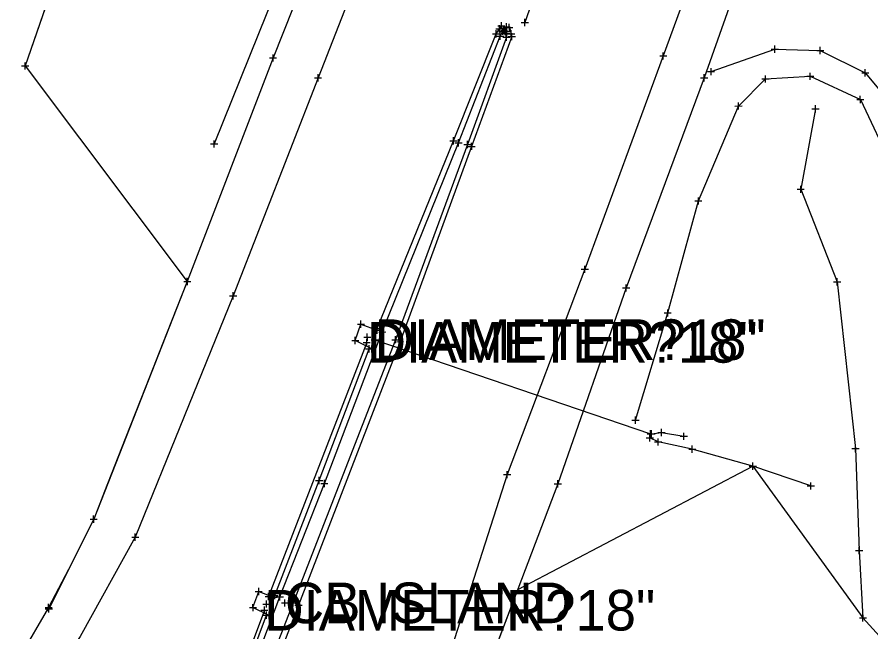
# Model space of a CAD drawing. Extents: x -1 to 1157254, y -1 to 2021979.
# Drawn here: x 1151479.8 to 1151631, y 2018989.6 to 2019098.4 of the extents above; entities that cross this region are included whole.
import ezdxf

# ---------------------------------------------------------------- set-up
doc = ezdxf.new("R2010")
doc.units = 0
for name, color, linetype in [('S_BUILDING_ANNOT', 7, 'Continuous'), ('S_CTL_TABLE', 7, 'Continuous'), ('S_DITCHLINE', 7, 'Continuous'), ('S_DRIVEWAY_ANNOT', 7, 'Continuous'), ('S_EDGE_BITUMINOUS_ANNOT', 7, 'Continuous'), ('S_EDGE_CONCRETE', 7, 'Continuous'), ('S_EDGE_CONCRETE_ANNOT', 7, 'Continuous'), ('S_EDGE_PAVEMENT', 7, 'Continuous'), ('S_ELECTRIC_UTILITIES', 7, 'Continuous'), ('S_ENV_CONSTRAINT', 7, 'Continuous'), ('S_FLAG_POLE', 7, 'Continuous'), ('S_GAS_PUMP_ISLAND_ANNOT', 7, 'Continuous'), ('S_GATE', 7, 'Continuous')]:
    doc.layers.add(name, color=color, linetype=linetype)

msp = doc.modelspace()

# ---------------------------------------------------------------- linework, layer by layer
at = {"layer": 'S_BUILDING_ANNOT'}
for p, q in [((1151565.25, 2019095.72), (1151565.24, 2019097)), ((1151565.58, 2019096.26), (1151565.58, 2019097.53)), ((1151566.5, 2019096.07), (1151566.49, 2019097.35)), ((1151567, 2019095.95), (1151566.99, 2019097.23)), ((1151569.11, 2019097.46), (1151570.38, 2019097.46)), ((1151569.75, 2019096.83), (1151569.74, 2019098.1)), ((1151569.75, 2019097.46), (1151569.75, 2019097.46)), ((1151564.01, 2019095.47), (1151565.28, 2019095.47)), ((1151564.61, 2019096.36), (1151565.88, 2019096.36)), ((1151564.65, 2019094.84), (1151564.65, 2019096.11)), ((1151564.65, 2019095.47), (1151564.65, 2019095.47)), ((1151564.94, 2019096.89), (1151566.22, 2019096.89)), ((1151565.18, 2019095.9), (1151566.45, 2019095.91)), ((1151565.25, 2019096.36), (1151565.25, 2019096.36)), ((1151565.37, 2019094.41), (1151565.36, 2019095.68)), ((1151565.42, 2019096.07), (1151566.69, 2019096.07)), ((1151565.58, 2019096.89), (1151565.58, 2019096.89)), ((1151565.64, 2019095.89), (1151566.92, 2019095.89)), ((1151565.81, 2019095.51), (1151567.09, 2019095.52)), ((1151565.82, 2019095.27), (1151565.82, 2019096.54)), ((1151565.82, 2019095.91), (1151565.82, 2019095.91)), ((1151565.86, 2019096.71), (1151567.13, 2019096.71)), ((1151565.94, 2019095.89), (1151567.21, 2019095.9)), ((1151566.06, 2019095.44), (1151566.06, 2019096.71)), ((1151566.06, 2019096.07), (1151566.06, 2019096.07)), ((1151566.28, 2019095.25), (1151566.28, 2019096.52)), ((1151566.28, 2019095.89), (1151566.28, 2019095.89)), ((1151566.36, 2019096.59), (1151567.63, 2019096.59)), ((1151566.45, 2019094.88), (1151566.45, 2019096.15)), ((1151566.45, 2019095.51), (1151566.45, 2019095.51)), ((1151566.49, 2019094.24), (1151566.49, 2019095.51)), ((1151566.5, 2019096.71), (1151566.5, 2019096.71)), ((1151566.58, 2019095.26), (1151566.57, 2019096.53)), ((1151566.57, 2019095.89), (1151566.57, 2019095.89)), ((1151566.67, 2019095.49), (1151567.94, 2019095.49)), ((1151567, 2019096.59), (1151567, 2019096.59)), ((1151567.31, 2019094.86), (1151567.31, 2019096.13)), ((1151567.31, 2019095.49), (1151567.31, 2019095.49)), ((1151567.44, 2019094.33), (1151567.44, 2019095.6)), ((1151564.73, 2019095.04), (1151566, 2019095.05)), ((1151565.36, 2019095.05), (1151565.36, 2019095.05)), ((1151565.86, 2019094.88), (1151567.13, 2019094.88)), ((1151566.49, 2019094.88), (1151566.49, 2019094.88)), ((1151566.8, 2019094.97), (1151568.08, 2019094.97)), ((1151567.44, 2019094.97), (1151567.44, 2019094.97)), ((1151613.36, 2019092.77), (1151614.64, 2019092.77)), ((1151614, 2019092.13), (1151614, 2019093.4)), ((1151614, 2019092.77), (1151614, 2019092.77)), ((1151621.42, 2019092.51), (1151622.7, 2019092.51)), ((1151622.06, 2019091.88), (1151622.06, 2019093.15)), ((1151622.06, 2019092.51), (1151622.06, 2019092.51)), ((1151524.51, 2019091.21), (1151525.78, 2019091.21)), ((1151525.15, 2019090.57), (1151525.15, 2019091.84)), ((1151525.15, 2019091.21), (1151525.15, 2019091.21)), ((1151593.63, 2019091.55), (1151594.9, 2019091.55)), ((1151594.26, 2019090.91), (1151594.26, 2019092.18)), ((1151594.26, 2019091.55), (1151594.26, 2019091.55)), ((1151602.72, 2019088.15), (1151602.71, 2019089.42)), ((1151533.12, 2019087.05), (1151533.12, 2019088.32)), ((1151601.48, 2019087.06), (1151601.48, 2019088.33)), ((1151602.08, 2019088.78), (1151603.35, 2019088.79)), ((1151602.71, 2019088.79), (1151602.71, 2019088.79)), ((1151629.4, 2019088.57), (1151630.67, 2019088.57)), ((1151630.03, 2019087.94), (1151630.03, 2019089.21)), ((1151630.03, 2019088.57), (1151630.03, 2019088.57)), ((1151532.48, 2019087.68), (1151533.75, 2019087.68)), ((1151533.12, 2019087.68), (1151533.12, 2019087.68)), ((1151600.85, 2019087.7), (1151602.12, 2019087.7)), ((1151601.48, 2019087.7), (1151601.48, 2019087.7)), ((1151620.59, 2019082.19), (1151621.86, 2019082.19)), ((1151621.23, 2019081.56), (1151621.22, 2019082.83)), ((1151621.22, 2019082.19), (1151621.22, 2019082.19)), ((1151556.46, 2019076.53), (1151557.73, 2019076.53)), ((1151557.1, 2019075.89), (1151557.09, 2019077.16)), ((1151557.09, 2019076.53), (1151557.09, 2019076.53)), ((1151557.36, 2019076.17), (1151558.64, 2019076.18)), ((1151558, 2019075.54), (1151558, 2019076.81)), ((1151558, 2019076.17), (1151558, 2019076.17)), ((1151558.94, 2019075.88), (1151560.21, 2019075.89)), ((1151559.58, 2019075.25), (1151559.58, 2019076.52)), ((1151559.58, 2019075.88), (1151559.58, 2019075.88)), ((1151560.33, 2019074.91), (1151560.32, 2019076.19)), ((1151559.69, 2019075.55), (1151560.96, 2019075.55)), ((1151560.32, 2019075.55), (1151560.32, 2019075.55)), ((1151618.59, 2019067.31), (1151618.59, 2019068.58)), ((1151617.95, 2019067.94), (1151619.23, 2019067.95)), ((1151618.59, 2019067.94), (1151618.59, 2019067.94)), ((1151579.72, 2019053.78), (1151580.99, 2019053.78)), ((1151580.36, 2019053.14), (1151580.36, 2019054.42)), ((1151580.36, 2019053.78), (1151580.36, 2019053.78)), ((1151509.34, 2019051.62), (1151510.61, 2019051.63)), ((1151509.98, 2019050.99), (1151509.97, 2019052.26)), ((1151509.97, 2019051.62), (1151509.97, 2019051.62)), ((1151625.04, 2019050.92), (1151625.04, 2019052.19)), ((1151587.05, 2019050.48), (1151588.32, 2019050.49)), ((1151587.68, 2019049.85), (1151587.68, 2019051.12)), ((1151587.68, 2019050.48), (1151587.68, 2019050.48)), ((1151624.4, 2019051.56), (1151625.67, 2019051.56)), ((1151625.04, 2019051.56), (1151625.04, 2019051.56)), ((1151517.47, 2019049.1), (1151518.74, 2019049.1)), ((1151518.11, 2019048.46), (1151518.1, 2019049.74)), ((1151518.11, 2019049.1), (1151518.11, 2019049.1)), ((1151540.08, 2019044.07), (1151541.36, 2019044.07)), ((1151540.72, 2019043.43), (1151540.72, 2019044.71)), ((1151540.72, 2019044.07), (1151540.72, 2019044.07)), ((1151542.94, 2019043.3), (1151544.21, 2019043.31)), ((1151542.97, 2019043.01), (1151544.24, 2019043.01)), ((1151543.58, 2019042.67), (1151543.58, 2019043.94)), ((1151543.58, 2019043.3), (1151543.58, 2019043.3)), ((1151543.6, 2019042.38), (1151543.6, 2019043.65)), ((1151543.6, 2019043.01), (1151543.6, 2019043.01)), ((1151543.87, 2019042.68), (1151545.14, 2019042.69)), ((1151544.51, 2019042.05), (1151544.5, 2019043.32)), ((1151544.5, 2019042.69), (1151544.5, 2019042.69)), ((1151539.08, 2019041.16), (1151540.35, 2019041.17)), ((1151539.72, 2019040.53), (1151539.71, 2019041.8)), ((1151539.71, 2019041.17), (1151539.71, 2019041.17)), ((1151541.21, 2019041.78), (1151542.48, 2019041.78)), ((1151541.21, 2019041.78), (1151542.48, 2019041.78)), ((1151541.74, 2019040.21), (1151541.74, 2019041.48)), ((1151541.74, 2019040.21), (1151541.74, 2019041.48)), ((1151541.85, 2019041.14), (1151541.84, 2019042.42)), ((1151541.85, 2019041.14), (1151541.84, 2019042.42)), ((1151541.84, 2019041.78), (1151541.84, 2019041.78)), ((1151541.84, 2019041.78), (1151541.84, 2019041.78)), ((1151542.51, 2019041.32), (1151543.78, 2019041.32)), ((1151542.51, 2019041.32), (1151543.78, 2019041.32)), ((1151543.15, 2019040.69), (1151543.15, 2019041.96)), ((1151543.15, 2019040.69), (1151543.15, 2019041.96)), ((1151543.15, 2019041.32), (1151543.15, 2019041.32)), ((1151543.15, 2019041.32), (1151543.15, 2019041.32)), ((1151546.17, 2019041.31), (1151547.45, 2019041.31)), ((1151546.81, 2019040.68), (1151546.81, 2019041.95)), ((1151546.81, 2019041.31), (1151546.81, 2019041.31)), ((1151547.64, 2019040.34), (1151547.63, 2019041.61)), ((1151541.1, 2019040.84), (1151542.38, 2019040.85)), ((1151541.1, 2019040.84), (1151542.38, 2019040.85)), ((1151541.55, 2019039.72), (1151542.83, 2019039.72)), ((1151541.74, 2019040.85), (1151541.74, 2019040.85)), ((1151541.74, 2019040.85), (1151541.74, 2019040.85)), ((1151542.02, 2019039.68), (1151543.3, 2019039.69)), ((1151542.19, 2019039.08), (1151542.19, 2019040.35)), ((1151542.19, 2019039.72), (1151542.19, 2019039.72)), ((1151542.66, 2019039.05), (1151542.66, 2019040.32)), ((1151542.66, 2019039.69), (1151542.66, 2019039.69)), ((1151547, 2019040.97), (1151548.27, 2019040.98)), ((1151547.64, 2019040.98), (1151547.64, 2019040.98)), ((1151591.38, 2019024.64), (1151592.65, 2019024.64)), ((1151591.52, 2019024.67), (1151592.8, 2019024.68)), ((1151591.89, 2019023.31), (1151591.89, 2019024.58)), ((1151592.02, 2019024), (1151592.02, 2019025.28)), ((1151592.02, 2019024.64), (1151592.02, 2019024.64)), ((1151592.16, 2019024.04), (1151592.16, 2019025.31)), ((1151592.16, 2019024.68), (1151592.16, 2019024.68)), ((1151593.32, 2019024.89), (1151594.59, 2019024.9)), ((1151593.96, 2019024.26), (1151593.96, 2019025.53)), ((1151593.96, 2019024.9), (1151593.96, 2019024.9)), ((1151597.9, 2019023.57), (1151597.89, 2019024.85)), ((1151591.25, 2019023.94), (1151592.52, 2019023.95)), ((1151591.89, 2019023.94), (1151591.89, 2019023.94)), ((1151592.72, 2019023.21), (1151594, 2019023.21)), ((1151593.36, 2019022.57), (1151593.36, 2019023.85)), ((1151593.36, 2019023.21), (1151593.36, 2019023.21)), ((1151597.26, 2019024.21), (1151598.53, 2019024.21)), ((1151597.9, 2019024.21), (1151597.9, 2019024.21)), ((1151598.76, 2019021.92), (1151600.03, 2019021.92)), ((1151599.4, 2019021.29), (1151599.4, 2019022.56)), ((1151599.4, 2019021.92), (1151599.4, 2019021.92)), ((1151627.67, 2019022.06), (1151628.94, 2019022.07)), ((1151628.31, 2019021.43), (1151628.31, 2019022.7)), ((1151628.31, 2019022.06), (1151628.31, 2019022.06)), ((1151609.47, 2019018.92), (1151610.74, 2019018.93)), ((1151610.11, 2019018.29), (1151610.1, 2019019.56)), ((1151610.1, 2019018.93), (1151610.1, 2019018.93)), ((1151533.31, 2019015.75), (1151533.3, 2019017.02)), ((1151565.98, 2019017.43), (1151567.26, 2019017.43)), ((1151566.62, 2019016.8), (1151566.62, 2019018.07)), ((1151566.62, 2019017.43), (1151566.62, 2019017.43)), ((1151532.67, 2019016.39), (1151533.94, 2019016.39)), ((1151533.3, 2019016.39), (1151533.3, 2019016.39)), ((1151533.61, 2019015.87), (1151534.88, 2019015.87)), ((1151534.25, 2019015.23), (1151534.24, 2019016.5)), ((1151534.24, 2019015.87), (1151534.24, 2019015.87)), ((1151574.96, 2019015.8), (1151576.23, 2019015.8)), ((1151575.6, 2019015.16), (1151575.59, 2019016.44)), ((1151575.6, 2019015.8), (1151575.6, 2019015.8)), ((1151619.75, 2019015.42), (1151621.02, 2019015.42)), ((1151620.38, 2019014.78), (1151620.38, 2019016.06)), ((1151620.38, 2019015.42), (1151620.38, 2019015.42)), ((1151492.75, 2019009.53), (1151494.02, 2019009.53)), ((1151493.39, 2019008.89), (1151493.38, 2019010.17)), ((1151493.39, 2019009.53), (1151493.39, 2019009.53)), ((1151500.12, 2019006.34), (1151501.39, 2019006.34)), ((1151500.76, 2019005.7), (1151500.76, 2019006.98)), ((1151500.76, 2019006.34), (1151500.76, 2019006.34)), ((1151628.3, 2019003.99), (1151629.57, 2019003.99)), ((1151628.94, 2019003.36), (1151628.93, 2019004.63)), ((1151628.94, 2019003.99), (1151628.94, 2019003.99)), ((1151522.62, 2018996.1), (1151522.61, 2018997.37)), ((1151521.98, 2018996.73), (1151523.25, 2018996.74)), ((1151522.62, 2018996.74), (1151522.62, 2018996.74)), ((1151523.73, 2018995.84), (1151525, 2018995.84)), ((1151523.73, 2018995.84), (1151525, 2018995.84)), ((1151524.37, 2018995.2), (1151524.36, 2018996.48)), ((1151524.37, 2018995.2), (1151524.36, 2018996.48)), ((1151524.37, 2018995.84), (1151524.37, 2018995.84)), ((1151524.37, 2018995.84), (1151524.37, 2018995.84)), ((1151524.62, 2018995.71), (1151525.89, 2018995.72)), ((1151524.81, 2018996.03), (1151526.08, 2018996.03)), ((1151525.25, 2018995.08), (1151525.25, 2018996.35)), ((1151525.25, 2018995.71), (1151525.25, 2018995.71)), ((1151525.45, 2018995.39), (1151525.45, 2018996.67)), ((1151525.45, 2018996.03), (1151525.45, 2018996.03)), ((1151525.73, 2018995.79), (1151527, 2018995.79)), ((1151526.37, 2018995.15), (1151526.36, 2018996.42)), ((1151526.36, 2018995.79), (1151526.36, 2018995.79)), ((1151485.4, 2018993.28), (1151485.4, 2018994.55)), ((1151485.44, 2018993.04), (1151485.44, 2018994.31)), ((1151521.61, 2018993.25), (1151521.6, 2018994.52)), ((1151523.37, 2018994.52), (1151524.64, 2018994.52)), ((1151523.37, 2018994.52), (1151524.64, 2018994.52)), ((1151524.01, 2018993.88), (1151524.01, 2018995.15)), ((1151524.01, 2018993.88), (1151524.01, 2018995.15)), ((1151524.01, 2018994.52), (1151524.01, 2018994.52)), ((1151524.01, 2018994.52), (1151524.01, 2018994.52)), ((1151526.63, 2018994.71), (1151527.9, 2018994.72)), ((1151527.26, 2018994.08), (1151527.26, 2018995.35)), ((1151527.26, 2018994.72), (1151527.26, 2018994.72)), ((1151528.06, 2018994.72), (1151529.33, 2018994.73)), ((1151528.7, 2018994.09), (1151528.69, 2018995.36)), ((1151528.69, 2018994.72), (1151528.69, 2018994.72)), ((1151529.02, 2018994.32), (1151530.29, 2018994.33)), ((1151529.65, 2018993.69), (1151529.65, 2018994.96)), ((1151529.65, 2018994.32), (1151529.65, 2018994.32)), ((1151484.77, 2018993.91), (1151486.04, 2018993.92)), ((1151484.8, 2018993.67), (1151486.08, 2018993.67)), ((1151485.4, 2018993.91), (1151485.4, 2018993.91)), ((1151485.44, 2018993.67), (1151485.44, 2018993.67)), ((1151520.97, 2018993.89), (1151522.24, 2018993.89)), ((1151521.6, 2018993.89), (1151521.6, 2018993.89)), ((1151522.98, 2018993.43), (1151524.25, 2018993.44)), ((1151522.98, 2018993.43), (1151524.25, 2018993.44)), ((1151523.61, 2018992.8), (1151523.61, 2018994.07)), ((1151523.61, 2018992.8), (1151523.61, 2018994.07)), ((1151523.61, 2018993.43), (1151523.61, 2018993.43)), ((1151523.61, 2018993.43), (1151523.61, 2018993.43)), ((1151524.02, 2018991.92), (1151524.02, 2018993.2)), ((1151524.46, 2018991.84), (1151524.45, 2018993.12)), ((1151629.61, 2018991.45), (1151629.61, 2018992.72)), ((1151523.38, 2018992.56), (1151524.66, 2018992.56)), ((1151523.82, 2018992.48), (1151525.09, 2018992.48)), ((1151524.02, 2018992.56), (1151524.02, 2018992.56)), ((1151524.45, 2018992.48), (1151524.45, 2018992.48)), ((1151628.98, 2018992.08), (1151630.25, 2018992.08)), ((1151629.61, 2018992.08), (1151629.61, 2018992.08))]:
    msp.add_line(p, q, dxfattribs=at)
at = {"layer": 'S_CTL_TABLE'}
for p, q in [((1151480.61, 2019089.78), (1151481.88, 2019089.78)), ((1151481.25, 2019089.15), (1151481.25, 2019090.42)), ((1151481.25, 2019089.78), (1151481.25, 2019089.78)), ((1151612.34, 2019086.85), (1151612.34, 2019088.12)), ((1151619.65, 2019087.95), (1151620.92, 2019087.95)), ((1151620.28, 2019087.32), (1151620.28, 2019088.59)), ((1151620.28, 2019087.95), (1151620.28, 2019087.95)), ((1151611.7, 2019087.48), (1151612.98, 2019087.48)), ((1151612.34, 2019087.48), (1151612.34, 2019087.48)), ((1151628.52, 2019083.85), (1151629.79, 2019083.85)), ((1151629.16, 2019083.21), (1151629.15, 2019084.48)), ((1151629.16, 2019083.85), (1151629.16, 2019083.85)), ((1151606.95, 2019082.69), (1151608.22, 2019082.7)), ((1151607.59, 2019082.06), (1151607.58, 2019083.33)), ((1151607.58, 2019082.69), (1151607.58, 2019082.69)), ((1151514.09, 2019075.97), (1151515.36, 2019075.98)), ((1151514.73, 2019075.34), (1151514.72, 2019076.61)), ((1151514.72, 2019075.97), (1151514.72, 2019075.97)), ((1151599.84, 2019065.88), (1151601.11, 2019065.89)), ((1151600.48, 2019065.25), (1151600.47, 2019066.52)), ((1151600.48, 2019065.89), (1151600.48, 2019065.89)), ((1151594.41, 2019046.06), (1151595.68, 2019046.06)), ((1151595.05, 2019045.42), (1151595.05, 2019046.69)), ((1151595.05, 2019046.06), (1151595.05, 2019046.06)), ((1151589.35, 2019026.43), (1151589.35, 2019027.7)), ((1151588.71, 2019027.06), (1151589.98, 2019027.07)), ((1151589.35, 2019027.06), (1151589.35, 2019027.06))]:
    msp.add_line(p, q, dxfattribs=at)
at = {"layer": 'S_DITCHLINE'}
for points in [[(1151543.15, 2019041.32), (1151592.02, 2019024.64)], [(1151541.74, 2019040.85), (1151524.37, 2018995.84)], [(1151523.61, 2018993.43), (1151507.63, 2018950.63)]]:
    msp.add_lwpolyline(points, dxfattribs=at)
at = {"layer": 'S_DRIVEWAY_ANNOT'}
for points in [[(1151621.22, 2019082.19), (1151618.59, 2019067.94), (1151625.04, 2019051.56), (1151628.31, 2019022.06), (1151628.94, 2019003.99), (1151629.61, 2018992.08)], [(1151620.38, 2019015.42), (1151610.1, 2019018.93), (1151599.4, 2019021.92), (1151593.36, 2019023.21), (1151591.89, 2019023.94), (1151592.16, 2019024.68), (1151593.96, 2019024.9), (1151597.9, 2019024.21)]]:
    msp.add_lwpolyline(points, dxfattribs=at)
at = {"layer": 'S_EDGE_BITUMINOUS_ANNOT'}
for points in [[(1151560.17, 2019219.27), (1151529.7, 2019182.33), (1151499.53, 2019142.67), (1151481.25, 2019089.78)], [(1151561.01, 2019193.82), (1151551.65, 2019168.5), (1151534.99, 2019126.29), (1151514.72, 2019075.97)], [(1151589.35, 2019027.06), (1151595.05, 2019046.06), (1151600.48, 2019065.89), (1151607.58, 2019082.69), (1151612.34, 2019087.48), (1151620.28, 2019087.95), (1151629.16, 2019083.85), (1151634.8, 2019071.93), (1151640.62, 2019051.85), (1151641.83, 2019028.01), (1151644.66, 2019001.93)]]:
    msp.add_lwpolyline(points, dxfattribs=at)
at = {"layer": 'S_EDGE_CONCRETE'}
for points in [[(1151665.32, 2019618.35), (1151663.56, 2019588.8), (1151659.6, 2019534.06), (1151659.4, 2019525.74), (1151657.28, 2019494.5), (1151654.81, 2019454.84), (1151653.17, 2019443.85), (1151648.96, 2019412.39), (1151646.72, 2019396.58), (1151641.51, 2019373.7), (1151635.32, 2019351.87), (1151623.96, 2019321.63), (1151610.64, 2019286.76), (1151594.67, 2019246.27), (1151580.05, 2019209.17), (1151567.29, 2019174.79), (1151552.07, 2019136.21), (1151533.12, 2019087.68), (1151518.11, 2019049.1), (1151500.76, 2019006.34), (1151490.98, 2018988.8), (1151485.56, 2018980.44)], [(1151704.86, 2019608.44), (1151705.24, 2019577.73), (1151704.48, 2019532.5), (1151704.1, 2019496.82), (1151702.93, 2019464.9), (1151696.53, 2019399.83), (1151690.62, 2019365.93), (1151683.01, 2019336.72), (1151673.3, 2019308.19), (1151660.32, 2019274.07), (1151648.25, 2019241.97), (1151632.02, 2019198.81), (1151613.86, 2019145.04), (1151594.26, 2019091.55), (1151580.36, 2019053.78), (1151566.62, 2019017.43), (1151557.29, 2018988.35), (1151554.82, 2018969.45), (1151556.64, 2018941.42)], [(1151543.58, 2019043.3), (1151557.09, 2019076.53), (1151564.65, 2019095.47), (1151565.25, 2019096.36), (1151565.58, 2019096.89), (1151566.5, 2019096.71), (1151567, 2019096.59), (1151567.31, 2019095.49), (1151567.44, 2019094.97), (1151560.32, 2019075.55), (1151547.64, 2019040.98), (1151529.65, 2018994.32), (1151519.62, 2018968.31)], [(1151525.45, 2018996.03), (1151533.3, 2019016.39), (1151542.19, 2019039.72)], [(1151515.87, 2018970.73), (1151524.02, 2018992.56)]]:
    msp.add_lwpolyline(points, dxfattribs=at)
at = {"layer": 'S_EDGE_CONCRETE_ANNOT'}
msp.add_lwpolyline([(1151627.44, 2019263.1), (1151621.76, 2019244.08), (1151614.37, 2019221.97), (1151600.26, 2019182.31), (1151585.92, 2019143.56), (1151569.75, 2019097.46)], dxfattribs=at)
at = {"layer": 'S_EDGE_PAVEMENT'}
msp.add_lwpolyline([(1151516.77, 2018970.5), (1151526.36, 2018995.79), (1151534.24, 2019015.87), (1151544.5, 2019042.69), (1151558, 2019076.17), (1151565.36, 2019095.05), (1151565.82, 2019095.91), (1151566.06, 2019096.07), (1151566.28, 2019095.89), (1151566.57, 2019095.89), (1151566.45, 2019095.51), (1151566.49, 2019094.88), (1151559.58, 2019075.88), (1151546.81, 2019041.31), (1151528.69, 2018994.72), (1151518.65, 2018968.8)], dxfattribs=at)
at = {"layer": 'S_ELECTRIC_UTILITIES'}
for points in [[(1151542.66, 2019039.69), (1151539.71, 2019041.17), (1151540.72, 2019044.07), (1151543.6, 2019043.01)], [(1151524.45, 2018992.48), (1151521.6, 2018993.89), (1151522.62, 2018996.74), (1151525.25, 2018995.71)]]:
    msp.add_lwpolyline(points, dxfattribs=at)
at = {"layer": 'S_ENV_CONSTRAINT'}
msp.add_lwpolyline([(1151602.71, 2019088.79), (1151614, 2019092.77), (1151622.06, 2019092.51), (1151630.03, 2019088.57), (1151637.83, 2019079.2), (1151643.66, 2019066.28), (1151647.89, 2019050.51), (1151651.17, 2019030.64), (1151652.03, 2019011.36), (1151652.16, 2018992.58), (1151652.67, 2018966.68)], dxfattribs=at)
at = {"layer": 'S_FLAG_POLE'}
for points in [[(1151715.45, 2019596.2), (1151715.07, 2019579.24), (1151714.27, 2019533.29), (1151711.4, 2019496.69), (1151710.6, 2019463.15), (1151708.62, 2019424.41), (1151704.78, 2019395.8), (1151698.68, 2019365.71), (1151690.54, 2019335.66), (1151679.94, 2019306.53), (1151667.35, 2019271.18), (1151655.32, 2019239.37), (1151639.86, 2019196.4), (1151634.5, 2019181.31), (1151615.7, 2019127.93), (1151601.48, 2019087.7), (1151587.68, 2019050.48), (1151575.6, 2019015.8), (1151564.48, 2018986.56), (1151559.43, 2018965.1), (1151561.48, 2018942.51)], [(1151651.74, 2019446.21), (1151642.73, 2019420.11), (1151639.07, 2019399.11), (1151633.8, 2019377.52), (1151627.31, 2019353.6), (1151616.19, 2019324.46), (1151605.67, 2019296.18), (1151599.02, 2019285.94), (1151584.12, 2019249.83), (1151584.02, 2019249.78), (1151575.24, 2019228.32), (1151565.98, 2019203.98), (1151563.23, 2019187.26), (1151551.04, 2019156.21), (1151544.92, 2019141), (1151525.15, 2019091.21), (1151509.97, 2019051.62), (1151493.39, 2019009.53), (1151485.44, 2018993.67), (1151485.4, 2018993.91), (1151479.82, 2018984.3)]]:
    msp.add_lwpolyline(points, dxfattribs=at)
at = {"layer": 'S_GAS_PUMP_ISLAND_ANNOT'}
for points in [[(1151486.46, 2019104.87), (1151483.2, 2019095.42), (1151481.25, 2019089.78), (1151509.97, 2019051.62), (1151506.31, 2019042.33), (1151502.65, 2019033.04), (1151498.99, 2019023.75), (1151495.33, 2019014.45), (1151493.39, 2019009.53), (1151488.92, 2019000.61), (1151485.4, 2018993.91), (1151480.39, 2018985.27)], [(1151564.94, 2018987.78), (1151568.49, 2018997.12), (1151610.1, 2019018.93), (1151629.61, 2018992.08), (1151652.67, 2018966.68)]]:
    msp.add_lwpolyline(points, dxfattribs=at)

# ---------------------------------------------------------------- texts
at = {"layer": 'S_BUILDING_ANNOT'}
for p in [(1151541.74, 2019037.25), (1151543.15, 2019037.72), (1151523.61, 2018989.83)]:
    msp.add_text('DIAMETER?18"', height=7.2, dxfattribs=at).set_placement(p)
at = {"layer": 'S_GATE'}
msp.add_text('CB ISLAND', height=7.2, dxfattribs=at).set_placement((1151527.26, 2018991.12))

doc.saveas('drawing.dxf')
